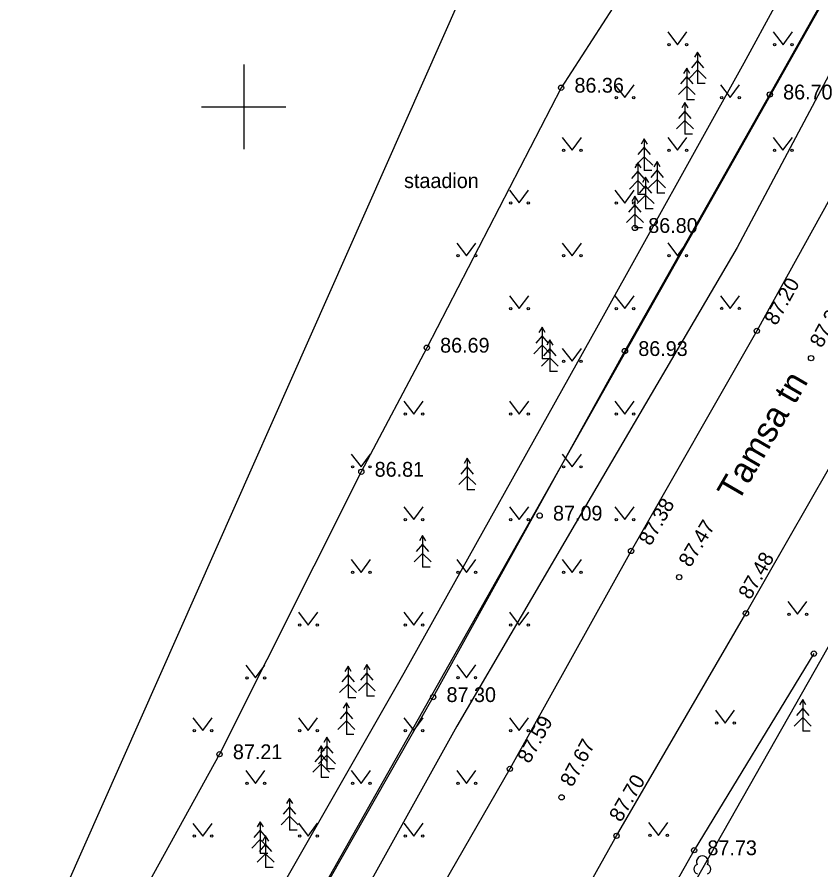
# Model space of a CAD drawing. Extents: x 648748 to 649126, y 6457789 to 6458252.
# Drawn here: x 648789.26 to 648827.35, y 6458013.84 to 6458054.26 of the extents above; entities that cross this region are included whole.
import ezdxf

# ---------------------------------------------------------------- set-up
doc = ezdxf.new("R2010")
doc.units = 0
for name, color, linetype in [('HALJASTUS', 7, 'Continuous'), ('KORGUS-EH2000', 7, 'Continuous'), ('PIIR', 7, 'Continuous'), ('PUU', 7, 'Continuous'), ('SITRASS', 7, 'Continuous'), ('TEE', 7, 'Continuous'), ('VORK', 7, 'Continuous'), ('VTRASS', 7, 'Continuous')]:
    doc.layers.add(name, color=color, linetype=linetype)

msp = doc.modelspace()

# ---------------------------------------------------------------- linework, layer by layer
at = {"layer": 'HALJASTUS'}
for p, q in [((648820.093, 6458053.549), (648820.557, 6458052.943)), ((648820.557, 6458052.943), (648821.002, 6458053.549)), ((648825.093, 6458053.549), (648825.557, 6458052.943)), ((648825.557, 6458052.943), (648826.002, 6458053.549)), ((648817.593, 6458051.049), (648818.057, 6458050.443)), ((648818.057, 6458050.443), (648818.502, 6458051.049)), ((648822.593, 6458051.049), (648823.057, 6458050.443)), ((648823.057, 6458050.443), (648823.502, 6458051.049)), ((648815.093, 6458048.549), (648815.557, 6458047.943)), ((648815.557, 6458047.943), (648816.002, 6458048.549)), ((648820.093, 6458048.549), (648820.557, 6458047.943)), ((648820.557, 6458047.943), (648821.002, 6458048.549)), ((648825.092, 6458048.553), (648825.555, 6458047.946)), ((648825.555, 6458047.946), (648826.001, 6458048.553)), ((648812.592, 6458046.053), (648813.055, 6458045.446)), ((648813.055, 6458045.446), (648813.501, 6458046.053)), ((648817.593, 6458046.049), (648818.057, 6458045.443)), ((648818.057, 6458045.443), (648818.502, 6458046.049)), ((648810.094, 6458043.549), (648810.557, 6458042.943)), ((648810.557, 6458042.943), (648811.003, 6458043.549)), ((648815.094, 6458043.549), (648815.557, 6458042.943)), ((648815.557, 6458042.943), (648816.003, 6458043.549)), ((648820.092, 6458043.553), (648820.555, 6458042.946)), ((648820.555, 6458042.946), (648821.001, 6458043.553)), ((648812.594, 6458041.049), (648813.057, 6458040.443)), ((648813.057, 6458040.443), (648813.503, 6458041.049)), ((648817.594, 6458041.049), (648818.057, 6458040.443)), ((648818.057, 6458040.443), (648818.503, 6458041.049)), ((648822.592, 6458041.053), (648823.055, 6458040.446)), ((648823.055, 6458040.446), (648823.501, 6458041.053)), ((648815.094, 6458038.549), (648815.557, 6458037.943)), ((648815.557, 6458037.943), (648816.003, 6458038.549)), ((648807.594, 6458036.049), (648808.057, 6458035.443)), ((648808.057, 6458035.443), (648808.503, 6458036.049)), ((648812.594, 6458036.049), (648813.057, 6458035.443)), ((648813.057, 6458035.443), (648813.503, 6458036.049)), ((648817.594, 6458036.049), (648818.057, 6458035.443)), ((648818.057, 6458035.443), (648818.503, 6458036.049)), ((648805.094, 6458033.549), (648805.557, 6458032.943)), ((648805.557, 6458032.943), (648806.003, 6458033.549)), ((648815.094, 6458033.549), (648815.557, 6458032.943)), ((648815.557, 6458032.943), (648816.003, 6458033.549)), ((648807.594, 6458031.049), (648808.057, 6458030.443)), ((648808.057, 6458030.443), (648808.503, 6458031.049)), ((648812.594, 6458031.049), (648813.057, 6458030.443)), ((648813.057, 6458030.443), (648813.503, 6458031.049)), ((648817.594, 6458031.049), (648818.057, 6458030.443)), ((648818.057, 6458030.443), (648818.503, 6458031.049)), ((648805.094, 6458028.549), (648805.557, 6458027.943)), ((648805.557, 6458027.943), (648806.003, 6458028.549)), ((648810.094, 6458028.549), (648810.557, 6458027.943)), ((648810.557, 6458027.943), (648811.003, 6458028.549)), ((648815.094, 6458028.549), (648815.557, 6458027.943)), ((648815.557, 6458027.943), (648816.003, 6458028.549)), ((648825.78, 6458026.565), (648826.243, 6458025.959)), ((648826.243, 6458025.959), (648826.689, 6458026.565)), ((648802.594, 6458026.049), (648803.057, 6458025.443)), ((648803.057, 6458025.443), (648803.503, 6458026.049)), ((648807.592, 6458026.053), (648808.055, 6458025.446)), ((648808.055, 6458025.446), (648808.501, 6458026.053)), ((648812.594, 6458026.049), (648813.057, 6458025.443)), ((648813.057, 6458025.443), (648813.503, 6458026.049)), ((648800.094, 6458023.549), (648800.557, 6458022.943)), ((648800.557, 6458022.943), (648801.003, 6458023.549)), ((648810.092, 6458023.553), (648810.555, 6458022.946)), ((648810.555, 6458022.946), (648811.001, 6458023.553)), ((648822.356, 6458021.406), (648822.819, 6458020.8)), ((648822.819, 6458020.8), (648823.265, 6458021.406)), ((648797.594, 6458021.049), (648798.057, 6458020.443)), ((648798.057, 6458020.443), (648798.503, 6458021.049)), ((648802.592, 6458021.053), (648803.055, 6458020.446)), ((648803.055, 6458020.446), (648803.501, 6458021.053)), ((648807.594, 6458021.049), (648808.057, 6458020.443)), ((648808.057, 6458020.443), (648808.503, 6458021.049)), ((648812.592, 6458021.053), (648813.055, 6458020.446)), ((648813.055, 6458020.446), (648813.501, 6458021.053)), ((648800.094, 6458018.549), (648800.557, 6458017.943)), ((648800.557, 6458017.943), (648801.003, 6458018.549)), ((648805.094, 6458018.549), (648805.557, 6458017.943)), ((648805.557, 6458017.943), (648806.003, 6458018.549)), ((648810.094, 6458018.549), (648810.557, 6458017.943)), ((648810.557, 6458017.943), (648811.003, 6458018.549)), ((648797.594, 6458016.049), (648798.057, 6458015.443)), ((648798.057, 6458015.443), (648798.503, 6458016.049)), ((648802.592, 6458016.053), (648803.055, 6458015.446)), ((648803.055, 6458015.446), (648803.501, 6458016.053)), ((648807.592, 6458016.053), (648808.055, 6458015.446)), ((648808.055, 6458015.446), (648808.501, 6458016.053)), ((648819.188, 6458016.083), (648819.652, 6458015.476)), ((648819.652, 6458015.476), (648820.097, 6458016.083))]:
    msp.add_line(p, q, dxfattribs=at)
msp.add_lwpolyline([(648827.017, 6458024.094), (648821.343, 6458014.775), (648815.332, 6458004.108), (648809.727, 6457994.028)], dxfattribs=at)
for centre in [(648820.156, 6458052.943), (648820.985, 6458052.943), (648825.156, 6458052.943), (648825.985, 6458052.943), (648817.656, 6458050.443), (648818.485, 6458050.443), (648822.656, 6458050.443), (648823.485, 6458050.443), (648815.156, 6458047.943), (648815.985, 6458047.943), (648820.156, 6458047.943), (648820.985, 6458047.943), (648825.154, 6458047.946), (648825.983, 6458047.946), (648812.654, 6458045.446), (648813.483, 6458045.446), (648817.656, 6458045.443), (648818.485, 6458045.443), (648810.156, 6458042.943), (648810.985, 6458042.943), (648815.156, 6458042.943), (648815.985, 6458042.943), (648820.154, 6458042.946), (648820.983, 6458042.946), (648812.656, 6458040.443), (648813.485, 6458040.443), (648817.656, 6458040.443), (648818.485, 6458040.443), (648822.654, 6458040.446), (648823.483, 6458040.446), (648815.156, 6458037.943), (648815.985, 6458037.943), (648807.656, 6458035.443), (648808.485, 6458035.443), (648812.656, 6458035.443), (648813.485, 6458035.443), (648817.656, 6458035.443), (648818.485, 6458035.443), (648805.156, 6458032.943), (648805.985, 6458032.943), (648815.156, 6458032.943), (648815.985, 6458032.943), (648807.656, 6458030.443), (648808.485, 6458030.443), (648812.656, 6458030.443), (648813.485, 6458030.443), (648817.656, 6458030.443), (648818.485, 6458030.443), (648805.156, 6458027.943), (648805.985, 6458027.943), (648810.156, 6458027.943), (648810.985, 6458027.943), (648815.156, 6458027.943), (648815.985, 6458027.943), (648825.842, 6458025.959), (648826.671, 6458025.959), (648802.656, 6458025.443), (648803.485, 6458025.443), (648807.654, 6458025.446), (648808.483, 6458025.446), (648812.656, 6458025.443), (648813.485, 6458025.443), (648800.156, 6458022.943), (648800.985, 6458022.943), (648810.154, 6458022.946), (648810.983, 6458022.946), (648822.418, 6458020.8), (648823.247, 6458020.8), (648797.656, 6458020.443), (648798.485, 6458020.443), (648802.654, 6458020.446), (648803.483, 6458020.446), (648807.656, 6458020.443), (648808.485, 6458020.443), (648812.654, 6458020.446), (648813.483, 6458020.446), (648800.156, 6458017.943), (648800.985, 6458017.943), (648805.156, 6458017.943), (648805.985, 6458017.943), (648810.156, 6458017.943), (648810.985, 6458017.943), (648797.656, 6458015.443), (648798.485, 6458015.443), (648802.654, 6458015.446), (648803.483, 6458015.446), (648807.654, 6458015.446), (648808.483, 6458015.446), (648819.251, 6458015.476), (648820.08, 6458015.476)]:
    msp.add_circle(centre, 0.055, dxfattribs=at)
at = {"layer": 'KORGUS-EH2000'}
for centre in [(648815.041, 6458050.907), (648824.931, 6458050.586), (648818.538, 6458044.263), (648824.317, 6458039.384), (648808.674, 6458038.587), (648818.066, 6458038.429), (648826.886, 6458038.092), (648805.571, 6458032.708), (648814.024, 6458030.632), (648818.356, 6458028.958), (648820.632, 6458027.716), (648823.8, 6458025.997), (648827.017, 6458024.094), (648808.978, 6458022.031), (648798.852, 6458019.324), (648812.613, 6458018.629), (648815.064, 6458017.283), (648817.667, 6458015.456), (648821.343, 6458014.775)]:
    msp.add_circle(centre, 0.125, dxfattribs=at)
at = {"layer": 'PIIR'}
for p, q in [((648868.92, 6458128.41), (648793.25, 6457994.41)), ((648796.52, 6457969.47), (648863.67, 6458087.81))]:
    msp.add_line(p, q, dxfattribs=at)
at = {"layer": 'PUU'}
for p, q in [((648821.512, 6458052.6), (648821.362, 6458052.35)), ((648821.662, 6458052.35), (648821.512, 6458052.6)), ((648821.512, 6458052.6), (648821.512, 6458051.1)), ((648821.512, 6458052.2), (648821.212, 6458051.85)), ((648821.812, 6458051.85), (648821.512, 6458052.2)), ((648820.996, 6458051.837), (648820.846, 6458051.587)), ((648821.146, 6458051.587), (648820.996, 6458051.837)), ((648820.996, 6458051.837), (648820.996, 6458050.337)), ((648820.996, 6458051.437), (648820.696, 6458051.087)), ((648821.296, 6458051.087), (648820.996, 6458051.437)), ((648821.512, 6458051.75), (648821.112, 6458051.35)), ((648821.912, 6458051.35), (648821.512, 6458051.75)), ((648820.996, 6458050.987), (648820.596, 6458050.587)), ((648821.396, 6458050.587), (648820.996, 6458050.987)), ((648821.872, 6458051.1), (648821.512, 6458051.1)), ((648820.909, 6458050.204), (648820.759, 6458049.954)), ((648821.059, 6458049.954), (648820.909, 6458050.204)), ((648820.909, 6458050.204), (648820.909, 6458048.704)), ((648821.356, 6458050.337), (648820.996, 6458050.337)), ((648820.909, 6458049.804), (648820.609, 6458049.454)), ((648821.209, 6458049.454), (648820.909, 6458049.804)), ((648820.909, 6458049.354), (648820.509, 6458048.954)), ((648821.309, 6458048.954), (648820.909, 6458049.354)), ((648821.269, 6458048.704), (648820.909, 6458048.704)), ((648818.983, 6458048.487), (648818.833, 6458048.237)), ((648819.133, 6458048.237), (648818.983, 6458048.487)), ((648818.983, 6458048.487), (648818.983, 6458046.987)), ((648818.983, 6458048.087), (648818.683, 6458047.737)), ((648819.283, 6458047.737), (648818.983, 6458048.087)), ((648818.679, 6458047.354), (648818.529, 6458047.104)), ((648818.983, 6458047.637), (648818.583, 6458047.237)), ((648818.829, 6458047.104), (648818.679, 6458047.354)), ((648818.679, 6458047.354), (648818.679, 6458045.854)), ((648819.383, 6458047.237), (648818.983, 6458047.637)), ((648819.589, 6458047.411), (648819.439, 6458047.161)), ((648819.739, 6458047.161), (648819.589, 6458047.411)), ((648819.589, 6458047.411), (648819.589, 6458045.911)), ((648818.679, 6458046.954), (648818.379, 6458046.604)), ((648818.979, 6458046.604), (648818.679, 6458046.954)), ((648819.343, 6458046.987), (648818.983, 6458046.987)), ((648819.589, 6458047.011), (648819.289, 6458046.661)), ((648819.889, 6458046.661), (648819.589, 6458047.011)), ((648819.047, 6458046.666), (648818.897, 6458046.416)), ((648819.197, 6458046.416), (648819.047, 6458046.666)), ((648819.047, 6458046.666), (648819.047, 6458045.166)), ((648819.589, 6458046.561), (648819.189, 6458046.161)), ((648819.989, 6458046.161), (648819.589, 6458046.561)), ((648818.679, 6458046.504), (648818.279, 6458046.104)), ((648819.079, 6458046.104), (648818.679, 6458046.504)), ((648819.047, 6458046.266), (648818.747, 6458045.916)), ((648819.347, 6458045.916), (648819.047, 6458046.266)), ((648818.538, 6458045.763), (648818.388, 6458045.513)), ((648818.688, 6458045.513), (648818.538, 6458045.763)), ((648818.538, 6458045.763), (648818.538, 6458044.263)), ((648819.047, 6458045.816), (648818.647, 6458045.416)), ((648819.039, 6458045.854), (648818.679, 6458045.854)), ((648819.447, 6458045.416), (648819.047, 6458045.816)), ((648819.949, 6458045.911), (648819.589, 6458045.911)), ((648818.538, 6458045.363), (648818.238, 6458045.013)), ((648818.838, 6458045.013), (648818.538, 6458045.363)), ((648818.538, 6458044.913), (648818.138, 6458044.513)), ((648818.938, 6458044.513), (648818.538, 6458044.913)), ((648819.407, 6458045.166), (648819.047, 6458045.166)), ((648818.898, 6458044.263), (648818.538, 6458044.263)), ((648814.141, 6458039.554), (648813.991, 6458039.304)), ((648814.291, 6458039.304), (648814.141, 6458039.554)), ((648814.141, 6458039.554), (648814.141, 6458038.054)), ((648814.141, 6458039.154), (648813.841, 6458038.804)), ((648814.441, 6458038.804), (648814.141, 6458039.154)), ((648814.506, 6458038.956), (648814.356, 6458038.706)), ((648814.656, 6458038.706), (648814.506, 6458038.956)), ((648814.506, 6458038.956), (648814.506, 6458037.456)), ((648814.141, 6458038.704), (648813.741, 6458038.304)), ((648814.541, 6458038.304), (648814.141, 6458038.704)), ((648814.506, 6458038.556), (648814.206, 6458038.206)), ((648814.806, 6458038.206), (648814.506, 6458038.556)), ((648814.506, 6458038.106), (648814.106, 6458037.706)), ((648814.501, 6458038.054), (648814.141, 6458038.054)), ((648814.906, 6458037.706), (648814.506, 6458038.106)), ((648814.866, 6458037.456), (648814.506, 6458037.456)), ((648810.593, 6458033.353), (648810.443, 6458033.103)), ((648810.743, 6458033.103), (648810.593, 6458033.353)), ((648810.593, 6458033.353), (648810.593, 6458031.853)), ((648810.593, 6458032.953), (648810.293, 6458032.603)), ((648810.893, 6458032.603), (648810.593, 6458032.953)), ((648810.593, 6458032.503), (648810.193, 6458032.103)), ((648810.993, 6458032.103), (648810.593, 6458032.503)), ((648810.953, 6458031.853), (648810.593, 6458031.853)), ((648808.475, 6458029.685), (648808.325, 6458029.435)), ((648808.625, 6458029.435), (648808.475, 6458029.685)), ((648808.475, 6458029.685), (648808.475, 6458028.185)), ((648808.475, 6458029.285), (648808.175, 6458028.935)), ((648808.775, 6458028.935), (648808.475, 6458029.285)), ((648808.475, 6458028.835), (648808.075, 6458028.435)), ((648808.875, 6458028.435), (648808.475, 6458028.835)), ((648808.835, 6458028.185), (648808.475, 6458028.185)), ((648804.945, 6458023.498), (648804.795, 6458023.248)), ((648805.095, 6458023.248), (648804.945, 6458023.498)), ((648804.945, 6458023.498), (648804.945, 6458021.998)), ((648805.834, 6458023.579), (648805.684, 6458023.329)), ((648805.984, 6458023.329), (648805.834, 6458023.579)), ((648805.834, 6458023.579), (648805.834, 6458022.079)), ((648804.945, 6458023.098), (648804.645, 6458022.748)), ((648805.245, 6458022.748), (648804.945, 6458023.098)), ((648805.834, 6458023.179), (648805.534, 6458022.829)), ((648806.134, 6458022.829), (648805.834, 6458023.179)), ((648805.834, 6458022.729), (648805.434, 6458022.329)), ((648806.234, 6458022.329), (648805.834, 6458022.729)), ((648804.945, 6458022.648), (648804.545, 6458022.248)), ((648805.345, 6458022.248), (648804.945, 6458022.648)), ((648805.305, 6458021.998), (648804.945, 6458021.998)), ((648806.194, 6458022.079), (648805.834, 6458022.079)), ((648826.489, 6458021.911), (648826.339, 6458021.661)), ((648826.639, 6458021.661), (648826.489, 6458021.911)), ((648826.489, 6458021.911), (648826.489, 6458020.411)), ((648804.862, 6458021.752), (648804.712, 6458021.502)), ((648805.012, 6458021.502), (648804.862, 6458021.752)), ((648804.862, 6458021.752), (648804.862, 6458020.252)), ((648826.489, 6458021.511), (648826.189, 6458021.161)), ((648826.789, 6458021.161), (648826.489, 6458021.511)), ((648804.862, 6458021.352), (648804.562, 6458021.002)), ((648805.162, 6458021.002), (648804.862, 6458021.352)), ((648804.862, 6458020.902), (648804.462, 6458020.502)), ((648805.262, 6458020.502), (648804.862, 6458020.902)), ((648826.489, 6458021.061), (648826.089, 6458020.661)), ((648826.889, 6458020.661), (648826.489, 6458021.061)), ((648826.849, 6458020.411), (648826.489, 6458020.411)), ((648803.943, 6458020.127), (648803.793, 6458019.877)), ((648804.093, 6458019.877), (648803.943, 6458020.127)), ((648803.943, 6458020.127), (648803.943, 6458018.627)), ((648805.222, 6458020.252), (648804.862, 6458020.252)), ((648803.667, 6458019.718), (648803.517, 6458019.468)), ((648803.943, 6458019.727), (648803.643, 6458019.377)), ((648803.817, 6458019.468), (648803.667, 6458019.718)), ((648803.667, 6458019.718), (648803.667, 6458018.218)), ((648804.243, 6458019.377), (648803.943, 6458019.727)), ((648803.667, 6458019.318), (648803.367, 6458018.968)), ((648803.943, 6458019.277), (648803.543, 6458018.877)), ((648803.967, 6458018.968), (648803.667, 6458019.318)), ((648804.343, 6458018.877), (648803.943, 6458019.277)), ((648803.667, 6458018.868), (648803.267, 6458018.468)), ((648804.067, 6458018.468), (648803.667, 6458018.868)), ((648804.303, 6458018.627), (648803.943, 6458018.627)), ((648804.027, 6458018.218), (648803.667, 6458018.218)), ((648802.171, 6458017.233), (648802.021, 6458016.983)), ((648802.321, 6458016.983), (648802.171, 6458017.233)), ((648802.171, 6458017.233), (648802.171, 6458015.733)), ((648802.171, 6458016.833), (648801.871, 6458016.483)), ((648802.471, 6458016.483), (648802.171, 6458016.833)), ((648802.171, 6458016.383), (648801.771, 6458015.983)), ((648802.571, 6458015.983), (648802.171, 6458016.383)), ((648800.778, 6458016.126), (648800.628, 6458015.876)), ((648800.928, 6458015.876), (648800.778, 6458016.126)), ((648800.778, 6458016.126), (648800.778, 6458014.626)), ((648800.778, 6458015.726), (648800.478, 6458015.376)), ((648801.078, 6458015.376), (648800.778, 6458015.726)), ((648801.037, 6458015.46), (648800.887, 6458015.21)), ((648801.187, 6458015.21), (648801.037, 6458015.46)), ((648801.037, 6458015.46), (648801.037, 6458013.96)), ((648802.531, 6458015.733), (648802.171, 6458015.733)), ((648800.778, 6458015.276), (648800.378, 6458014.876)), ((648801.037, 6458015.06), (648800.737, 6458014.71)), ((648801.178, 6458014.876), (648800.778, 6458015.276)), ((648801.337, 6458014.71), (648801.037, 6458015.06)), ((648801.037, 6458014.61), (648800.637, 6458014.21)), ((648801.138, 6458014.626), (648800.778, 6458014.626)), ((648801.437, 6458014.21), (648801.037, 6458014.61)), ((648801.397, 6458013.96), (648801.037, 6458013.96))]:
    msp.add_line(p, q, dxfattribs=at)
for centre, radius, start, end in [((648821.734, 6458014.23), 0.277, 332.58, 207.42), ((648821.564, 6458013.882), 0.233, 109.022, 253.142), ((648821.904, 6458013.882), 0.233, 286.851, 70.986)]:
    msp.add_arc(centre, radius, start, end, dxfattribs=at)
at = {"layer": 'SITRASS'}
for points in [[(648838.183, 6458075.605), (648836.351, 6458076.524), (648834.032, 6458074.854), (648828.836, 6458070.077), (648823.373, 6458063.799), (648815.041, 6458050.907), (648808.674, 6458038.587), (648805.571, 6458032.708), (648798.852, 6458019.324), (648793.359, 6458009.366), (648788.414, 6457998.68), (648785.353, 6457991.074), (648783.686, 6457988.513), (648778.988, 6457980.101), (648777.337, 6457977.723), (648774.295, 6457973.649), (648772.508, 6457971.285), (648769.936, 6457967.433)], [(648840.698, 6458076.036), (648840.206, 6458074.518), (648835.992, 6458066.48), (648829.455, 6458054.737), (648823.386, 6458043.337), (648816.202, 6458031.074), (648810.097, 6458020.648), (648803.233, 6458008.294), (648797.369, 6457997.813), (648791.835, 6457987.5), (648788.847, 6457982.267), (648783.409, 6457971.182), (648777.403, 6457959.148), (648772.285, 6457949.688)], [(648771.558, 6457962.366), (648777.323, 6457971.169), (648780.294, 6457977.006), (648783.881, 6457983.462), (648786.386, 6457988.106), (648790.088, 6457993.164), (648795.127, 6458001.6), (648799.018, 6458008.179), (648807.603, 6458023.185), (648816.805, 6458039.666), (648823.715, 6458052.086), (648829.839, 6458063.342), (648833.461, 6458069.995), (648835.841, 6458074.502), (648836.926, 6458074.748), (648838.183, 6458075.605)], [(648772.534, 6457959.145), (648778.305, 6457968.987), (648782.296, 6457976.466), (648786.131, 6457983.091), (648788.533, 6457986.692), (648790.268, 6457990.62), (648793.726, 6457995.075), (648800.38, 6458006.925), (648808.978, 6458022.031), (648818.066, 6458038.429), (648824.931, 6458050.586), (648831.029, 6458061.413), (648834.793, 6458068.888), (648838.183, 6458075.605), (648839.481, 6458073.453), (648841.568, 6458071.264), (648846.872, 6458065.923), (648848.753, 6458063.394)]]:
    msp.add_lwpolyline(points, dxfattribs=at)
at = {"layer": 'TEE'}
for points in [[(648844.3, 6458074.59), (648841.568, 6458069.96), (648835.932, 6458060.036), (648830.008, 6458049.677), (648824.317, 6458039.384), (648818.356, 6458028.958), (648812.613, 6458018.629), (648806.656, 6458008.281), (648800.566, 6457997.472), (648794.382, 6457986.281), (648790.808, 6457979.567), (648784.572, 6457968.758), (648779.694, 6457960.62), (648774.527, 6457951.036)], [(648795.708, 6457976.678), (648799.747, 6457983.584), (648805.652, 6457994.165), (648811.974, 6458005.315), (648817.667, 6458015.456), (648823.8, 6458025.997), (648829.771, 6458036.425), (648835.506, 6458046.826), (648841.055, 6458057.292), (648846.734, 6458067.377), (648849.159, 6458071.672)]]:
    msp.add_lwpolyline(points, dxfattribs=at)
at = {"layer": 'VORK'}
for p, q in [((648800, 6458052), (648800, 6458048)), ((648798, 6458050), (648802, 6458050))]:
    msp.add_line(p, q, dxfattribs=at)
at = {"layer": 'VTRASS'}
msp.add_line((648818.874, 6458074.609), (648784.329, 6457996.666), dxfattribs=at)

# ---------------------------------------------------------------- texts
at = {"layer": 'HALJASTUS'}
msp.add_text('staadion', height=0.7, dxfattribs=at).set_placement((648807.598, 6458046.153))
at = {"layer": 'KORGUS-EH2000'}
for s, p in [(' 86.36', (648815.413, 6458050.674)), (' 86.70', (648825.303, 6458050.353)), (' 86.80', (648818.91, 6458044.029)), (' 86.69', (648809.046, 6458038.354)), (' 86.93', (648818.438, 6458038.196)), (' 86.81', (648805.943, 6458032.475)), (' 87.09', (648814.396, 6458030.399)), (' 87.30', (648809.35, 6458021.798)), (' 87.21', (648799.224, 6458019.091)), (' 87.73', (648821.715, 6458014.541))]:
    msp.add_text(s, height=0.7, dxfattribs=at).set_placement(p)
for s, rotation, p in [(' 87.20', 61.0643, (648825.11, 6458039.371)), (' 87.26', 61.4399, (648827.269, 6458038.308)), (' 87.38', 60.2406, (648819.149, 6458028.934)), (' 87.47', 58.9241, (648821.024, 6458027.915)), (' 87.48', 60.2055, (648823.873, 6458026.384)), (' 87.59', 60.9267, (648813.406, 6458018.615)), (' 87.67', 61.9104, (648815.445, 6458017.502)), (' 87.70', 59.8092, (648817.744, 6458015.842))]:
    msp.add_text(s, height=0.7, rotation=rotation, dxfattribs=at).set_placement(p)
at = {"layer": 'TEE'}
msp.add_text('Tamsa tn', height=1.2, rotation=59.8074, dxfattribs=at).set_placement((648823.417, 6458031.222))

doc.saveas('drawing.dxf')
